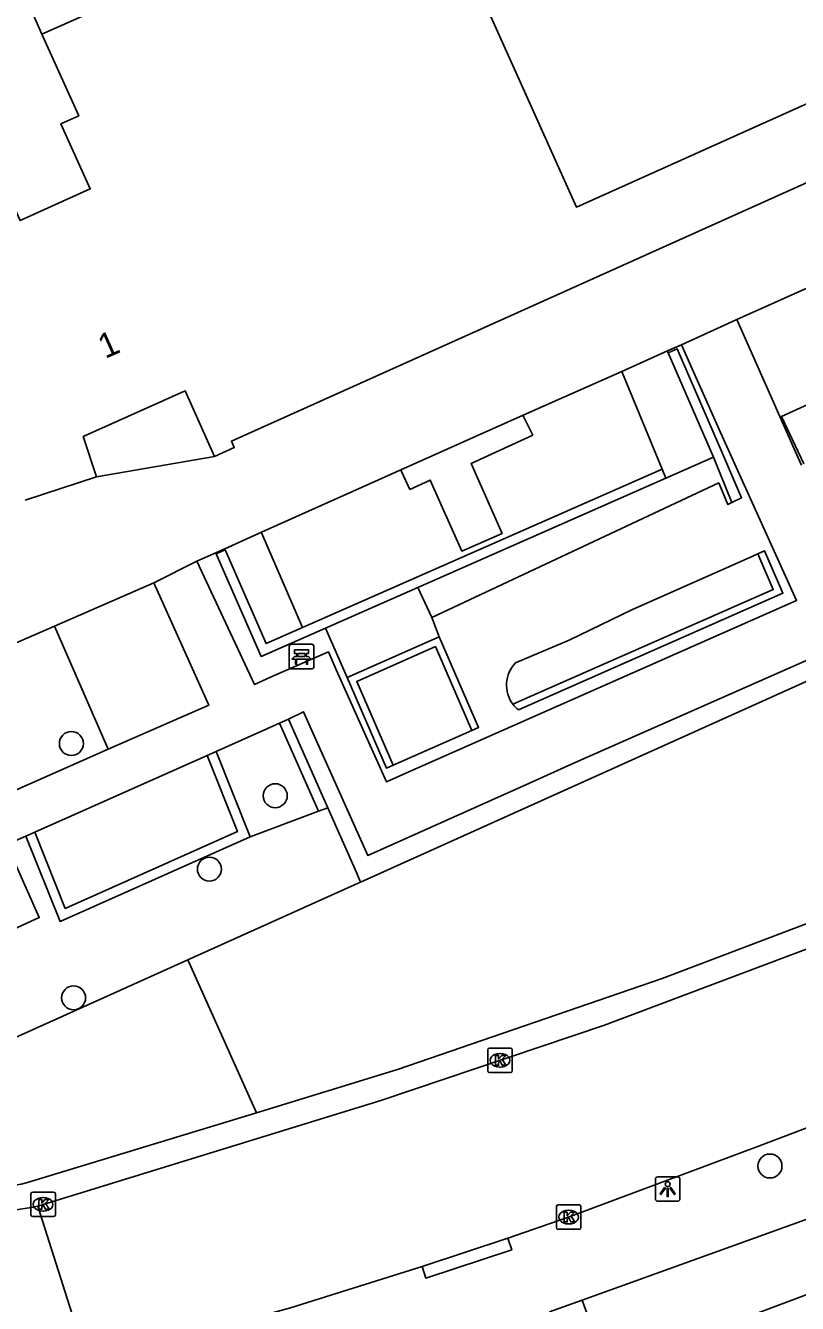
# Model space of a CAD drawing. Extents: x 161253 to 161848, y 384872 to 385383.
# Drawn here: x 161505.8 to 161537.3, y 385046.9 to 385099.1 of the extents above; entities that cross this region are included whole.
import ezdxf

# ---------------------------------------------------------------- set-up
doc = ezdxf.new("R2010")
doc.units = 0
for name, color, linetype in [('IMGEO_Bank', 7, 'Continuous'), ('IMGEO_Boom', 7, 'Continuous'), ('IMGEO_Groenvoorziening', 7, 'Continuous'), ('IMGEO_Haag', 7, 'Continuous'), ('IMGEO_Kolk', 7, 'Continuous'), ('IMGEO_Lichtpunt', 7, 'Continuous'), ('IMGEO_Pand', 7, 'Continuous'), ('IMGEO_Pand_nummerreeks', 7, 'Continuous'), ('IMGEO_Rijbaan_lokaal_open', 7, 'Continuous'), ('IMGEO_Voetpad_halfverhard', 7, 'Continuous'), ('IMGEO_Voetpad_open', 7, 'Continuous')]:
    doc.layers.add(name, color=color, linetype=linetype)

msp = doc.modelspace()

# ---------------------------------------------------------------- linework, layer by layer
at = {"layer": 'IMGEO_Bank'}
for p, q in [((161516.532, 385072.865), (161516.532, 385073.706)), ((161516.532, 385073.706), (161516.532, 385072.865)), ((161516.607, 385073.79), (161517.448, 385073.79)), ((161517.448, 385073.79), (161516.607, 385073.79)), ((161517.532, 385073.715), (161517.532, 385072.874)), ((161517.532, 385072.874), (161517.532, 385073.715)), ((161517.229, 385073.188), (161516.836, 385073.188)), ((161516.841, 385073.296), (161516.841, 385073.402)), ((161516.885, 385073.402), (161516.885, 385073.296)), ((161517.173, 385073.408), (161516.891, 385073.408)), ((161516.891, 385073.29), (161517.173, 385073.29)), ((161517.179, 385073.296), (161517.179, 385073.402)), ((161517.223, 385073.402), (161517.223, 385073.296)), ((161517.457, 385072.79), (161516.616, 385072.79)), ((161516.616, 385072.79), (161517.457, 385072.79))]:
    msp.add_line(p, q, dxfattribs=at)
for points in [[(161516.779, 385073.188), (161516.637, 385073.188), (161516.749, 385073.29), (161516.835, 385073.29)], [(161516.835, 385073.408), (161516.749, 385073.408), (161516.749, 385073.569), (161517.312, 385073.569), (161517.312, 385073.408), (161517.229, 385073.408)], [(161516.829, 385073.181), (161516.829, 385072.974), (161516.786, 385072.974), (161516.786, 385073.181)], [(161517.229, 385073.29), (161517.312, 385073.29), (161517.424, 385073.188), (161517.285, 385073.188)], [(161517.279, 385073.181), (161517.279, 385072.974), (161517.235, 385072.974), (161517.235, 385073.181)]]:
    msp.add_lwpolyline(points, dxfattribs=at)
for centre, radius, start, end in [((161516.61, 385073.712), 0.0779, 92.4484, 184.2845), ((161516.61, 385073.712), 0.0779, 92.4484, 184.2845), ((161517.454, 385073.712), 0.0779, 2.4484, 94.2845), ((161517.454, 385073.712), 0.0779, 2.4484, 94.2845), ((161516.779, 385073.181), 0.00671, 2.8957, 87.1043), ((161516.836, 385073.181), 0.00671, 92.8957, 177.1043), ((161516.834, 385073.401), 0.00671, 2.8957, 87.1043), ((161516.834, 385073.297), 0.00671, 272.8957, 357.1043), ((161516.891, 385073.401), 0.00671, 92.8957, 177.1043), ((161516.891, 385073.297), 0.00671, 182.8957, 267.1043), ((161517.173, 385073.401), 0.00671, 2.8957, 87.1043), ((161517.173, 385073.297), 0.00671, 272.8957, 357.1043), ((161517.23, 385073.401), 0.00671, 92.8957, 177.1043), ((161517.23, 385073.297), 0.00671, 182.8957, 267.1043), ((161517.228, 385073.181), 0.00671, 2.8957, 87.1043), ((161517.285, 385073.181), 0.00671, 92.8957, 177.1043), ((161516.61, 385072.868), 0.0779, 182.4484, 274.2845), ((161516.61, 385072.868), 0.0779, 182.4484, 274.2845), ((161517.454, 385072.868), 0.0779, 272.4484, 4.2845), ((161517.454, 385072.868), 0.0779, 272.4484, 4.2845)]:
    msp.add_arc(centre, radius, start, end, dxfattribs=at)
at = {"layer": 'IMGEO_Boom'}
for centre in [(161507.64, 385069.736), (161515.959, 385067.608), (161513.271, 385064.613), (161507.732, 385059.358), (161536.141, 385052.491)]:
    msp.add_circle(centre, 0.489, dxfattribs=at)
at = {"layer": 'IMGEO_Groenvoorziening'}
for points in [[(161583.611, 385090.971), (161578.405, 385089.13), (161576.826, 385088.455), (161555.221, 385080.061), (161546.898, 385076.445), (161519.439, 385064.08)], [(161531.994, 385085.686), (161531.96, 385085.764)], [(161530.093, 385084.931), (161530.127, 385084.856), (161531.742, 385080.936)], [(161521.079, 385080.91), (161521.108, 385080.845), (161521.452, 385080.111), (161522.284, 385080.497), (161523.576, 385077.597), (161525.215, 385078.314), (161523.949, 385081.175), (161526.462, 385082.332), (161526.104, 385083.067), (161526.072, 385083.138)], [(161531.894, 385080.566), (161533.832, 385081.43)], [(161534.588, 385079.584), (161534.415, 385079.501), (161534.05, 385080.378), (161522.346, 385074.89)], [(161517.068, 385074.475), (161515.417, 385078.314), (161515.394, 385078.365)], [(161513.896, 385077.693), (161513.917, 385077.647)], [(161525.765, 385073.031), (161527.955, 385073.955), (161530.531, 385075.211), (161535.315, 385077.339), (161535.644, 385077.485)], [(161520.77, 385068.857), (161523.981, 385070.274)], [(161517.723, 385066.971), (161514.93, 385065.934)], [(161519.439, 385064.08), (161519.266, 385064.472), (161518.098, 385067.11)], [(161505.007, 385065.612), (161506.332, 385062.63), (161504.42, 385061.76), (161502.997, 385064.717)], [(161519.439, 385064.08), (161519.074, 385063.916), (161512.396, 385060.909)], [(161501.094, 385055.82), (161512.396, 385060.909)], [(161512.396, 385060.909), (161515.187, 385054.666)]]:
    msp.add_lwpolyline(points, dxfattribs=at)
msp.add_arc((161526.68, 385072.123), 1.289, 135.2454, 217.3741, dxfattribs=at)
at = {"layer": 'IMGEO_Haag'}
for points in [[(161506.442, 385098.697), (161505.803, 385100.164)], [(161552.976, 385087.535), (161552.195, 385089.652), (161552.019, 385090.129), (161536.61, 385083.086), (161537.526, 385081.156)], [(161531.994, 385085.686), (161532.359, 385085.849), (161534.202, 385081.582), (161534.983, 385079.774), (161534.588, 385079.584)], [(161533.832, 385081.43), (161531.994, 385085.686)], [(161534.588, 385079.584), (161533.832, 385081.43)], [(161517.068, 385074.475), (161531.742, 385080.936)], [(161531.894, 385080.566), (161521.777, 385076.111)], [(161531.742, 385080.936), (161531.894, 385080.566)], [(161518.006, 385074.451), (161515.378, 385073.294), (161513.552, 385077.484), (161513.917, 385077.647)], [(161513.917, 385077.647), (161515.584, 385073.822), (161517.068, 385074.475)], [(161535.644, 385077.485), (161536.275, 385076.026), (161525.656, 385071.341)], [(161535.644, 385077.485), (161535.919, 385077.607), (161536.668, 385075.872), (161525.881, 385071.113)], [(161521.777, 385076.111), (161518.006, 385074.451)], [(161521.777, 385076.111), (161522.346, 385074.89)], [(161522.346, 385074.89), (161522.645, 385074.09)], [(161509.142, 385069.503), (161506.948, 385074.531)], [(161518.886, 385072.431), (161518.006, 385074.451)], [(161522.645, 385074.09), (161518.886, 385072.431)], [(161523.981, 385070.274), (161522.49, 385073.694), (161519.28, 385072.277), (161520.77, 385068.857)], [(161522.645, 385074.09), (161524.255, 385070.395), (161523.981, 385070.274)], [(161520.77, 385068.857), (161520.496, 385068.736), (161518.886, 385072.431)], [(161516.132, 385070.566), (161517.723, 385066.971)], [(161516.497, 385070.729), (161518.098, 385067.11)], [(161513.184, 385069.253), (161514.417, 385066.143), (161507.394, 385063.009), (161506.153, 385066.122)], [(161513.55, 385069.416), (161514.93, 385065.934)], [(161518.098, 385067.11), (161517.723, 385066.971)], [(161514.93, 385065.934), (161507.177, 385062.474), (161505.787, 385065.959)]]:
    msp.add_lwpolyline(points, dxfattribs=at)
msp.add_arc((161526.655, 385072.102), 1.256, 217.2933, 231.9478, dxfattribs=at)
at = {"layer": 'IMGEO_Kolk'}
for p, q in [((161524.626, 385056.381), (161524.626, 385057.233)), ((161524.701, 385057.307), (161525.553, 385057.307)), ((161525.114, 385057.087), (161525.139, 385057.087)), ((161525.627, 385057.233), (161525.627, 385056.381)), ((161525.137, 385056.527), (161525.112, 385056.527)), ((161525.553, 385056.307), (161524.701, 385056.307)), ((161505.988, 385050.5), (161505.988, 385051.352)), ((161506.063, 385051.426), (161506.915, 385051.426)), ((161506.989, 385051.352), (161506.989, 385050.5)), ((161506.476, 385051.206), (161506.501, 385051.206)), ((161527.428, 385049.98), (161527.428, 385050.832)), ((161527.503, 385050.906), (161528.355, 385050.906)), ((161528.429, 385050.832), (161528.429, 385049.98)), ((161506.915, 385050.426), (161506.063, 385050.426)), ((161506.499, 385050.646), (161506.474, 385050.646)), ((161527.916, 385050.686), (161527.941, 385050.686)), ((161528.355, 385049.906), (161527.503, 385049.906)), ((161527.939, 385050.126), (161527.914, 385050.126))]:
    msp.add_line(p, q, dxfattribs=at)
for points in [[(161524.626, 385056.381), (161524.626, 385057.233)], [(161524.701, 385057.307), (161525.553, 385057.307)], [(161524.947, 385057.007), (161525.07, 385057.007), (161525.07, 385056.856), (161525.2, 385057.007), (161525.364, 385057.007), (161525.218, 385056.856), (161525.371, 385056.607), (161525.219, 385056.607), (161525.134, 385056.771), (161525.07, 385056.704), (161525.07, 385056.607), (161524.947, 385056.607), (161524.947, 385057.007)], [(161525.627, 385057.233), (161525.627, 385056.381)], [(161525.553, 385056.307), (161524.701, 385056.307)], [(161505.988, 385050.5), (161505.988, 385051.352)], [(161506.063, 385051.426), (161506.915, 385051.426)], [(161506.989, 385051.352), (161506.989, 385050.5)], [(161506.309, 385051.126), (161506.432, 385051.126), (161506.432, 385050.975), (161506.562, 385051.126), (161506.726, 385051.126), (161506.58, 385050.975), (161506.733, 385050.726), (161506.581, 385050.726), (161506.496, 385050.89), (161506.432, 385050.823), (161506.432, 385050.726), (161506.309, 385050.726), (161506.309, 385051.126)], [(161527.428, 385049.98), (161527.428, 385050.832)], [(161527.503, 385050.906), (161528.355, 385050.906)], [(161528.429, 385050.832), (161528.429, 385049.98)], [(161506.915, 385050.426), (161506.063, 385050.426)], [(161527.749, 385050.606), (161527.872, 385050.606), (161527.872, 385050.455), (161528.002, 385050.606), (161528.166, 385050.606), (161528.02, 385050.455), (161528.173, 385050.206), (161528.021, 385050.206), (161527.936, 385050.37), (161527.872, 385050.303), (161527.872, 385050.206), (161527.749, 385050.206), (161527.749, 385050.606)], [(161528.355, 385049.906), (161527.503, 385049.906)]]:
    msp.add_lwpolyline(points, dxfattribs=at)
for centre, start, end in [((161524.703, 385057.231), 91.552, 178.448), ((161524.703, 385057.231), 91.552, 178.448), ((161525.551, 385057.231), 1.552, 88.448), ((161525.551, 385057.231), 1.552, 88.448), ((161524.703, 385056.383), 181.552, 268.448), ((161524.703, 385056.383), 181.552, 268.448), ((161525.551, 385056.383), 271.552, 358.448), ((161525.551, 385056.383), 271.552, 358.448), ((161506.065, 385051.35), 91.552, 178.448), ((161506.065, 385051.35), 91.552, 178.448), ((161506.913, 385051.35), 1.552, 88.448), ((161506.913, 385051.35), 1.552, 88.448), ((161527.505, 385050.83), 91.552, 178.448), ((161527.505, 385050.83), 91.552, 178.448), ((161528.353, 385050.83), 1.552, 88.448), ((161528.353, 385050.83), 1.552, 88.448), ((161506.065, 385050.502), 181.552, 268.448), ((161506.065, 385050.502), 181.552, 268.448), ((161506.913, 385050.502), 271.552, 358.448), ((161506.913, 385050.502), 271.552, 358.448), ((161527.505, 385049.982), 181.552, 268.448), ((161527.505, 385049.982), 181.552, 268.448), ((161528.353, 385049.982), 271.552, 358.448), ((161528.353, 385049.982), 271.552, 358.448)]:
    msp.add_arc(centre, 0.0765, start, end, dxfattribs=at)
for centre, major_axis, ratio, start_param, end_param in [((161525.113, 385056.807), (-0.387, 0.002), 0.722429, 4.712389, 7.853982), ((161525.138, 385056.807), (-0.39, 0.002), 0.717154, 1.570796, 4.712389), ((161506.475, 385050.926), (-0.387, 0.002), 0.722429, 4.712389, 7.853982), ((161506.5, 385050.926), (-0.39, 0.002), 0.717154, 1.570796, 4.712389), ((161527.915, 385050.406), (-0.387, 0.002), 0.722429, 4.712389, 7.853982), ((161527.94, 385050.406), (-0.39, 0.002), 0.717154, 1.570796, 4.712389)]:
    msp.add_ellipse(centre, major_axis=major_axis, ratio=ratio, start_param=start_param, end_param=end_param, dxfattribs=at)
at = {"layer": 'IMGEO_Lichtpunt'}
for p, q in [((161531.468, 385051.952), (161531.468, 385051.145)), ((161531.468, 385051.952), (161531.468, 385051.145)), ((161532.37, 385052.047), (161531.562, 385052.047)), ((161532.37, 385052.047), (161531.562, 385052.047)), ((161532.464, 385051.145), (161532.464, 385051.952)), ((161532.464, 385051.145), (161532.464, 385051.952)), ((161531.562, 385051.051), (161532.37, 385051.051)), ((161531.562, 385051.051), (161532.37, 385051.051))]:
    msp.add_line(p, q, dxfattribs=at)
for points in [[(161531.842, 385051.616), (161531.881, 385051.588), (161531.693, 385051.326), (161531.655, 385051.353), (161531.842, 385051.616)], [(161531.944, 385051.568), (161531.991, 385051.568), (161531.991, 385051.246), (161531.944, 385051.246), (161531.944, 385051.568)], [(161532.054, 385051.588), (161532.092, 385051.615), (161532.279, 385051.353), (161532.24, 385051.325), (161532.054, 385051.588)]]:
    msp.add_lwpolyline(points, dxfattribs=at)
msp.add_circle((161531.967, 385051.75), 0.0994, dxfattribs=at)
for centre, start, end in [((161531.562, 385051.952), 90, 180), ((161531.562, 385051.952), 90, 180), ((161532.37, 385051.952), 0, 90), ((161532.37, 385051.952), 0, 90), ((161531.562, 385051.145), 180, 270), ((161531.562, 385051.145), 180, 270), ((161532.37, 385051.145), 270, 0), ((161532.37, 385051.145), 270, 360)]:
    msp.add_arc(centre, 0.0946, start, end, dxfattribs=at)
at = {"layer": 'IMGEO_Pand'}
for points in [[(161544.216, 385098.993), (161543.409, 385098.631), (161543.475, 385098.484), (161528.242, 385091.641), (161524.736, 385099.445), (161540.026, 385106.314), (161540.114, 385106.118), (161540.85, 385106.449)], [(161509.432, 385100.917), (161509.76, 385100.187), (161506.442, 385098.697)], [(161506.442, 385098.697), (161507.939, 385095.366), (161507.216, 385095.041), (161508.413, 385092.378), (161505.548, 385091.091), (161505.089, 385092.114)], [(161544.216, 385098.993), (161545.617, 385095.875), (161544.78, 385095.5), (161544.654, 385095.78), (161514.171, 385082.086), (161514.288, 385081.826), (161513.477, 385081.462)], [(161508.662, 385080.628), (161508.122, 385082.268), (161512.277, 385084.134), (161513.477, 385081.462)], [(161508.662, 385080.628), (161505.758, 385079.671)], [(161535.556, 385046.459), (161541.46, 385048.676)]]:
    msp.add_lwpolyline(points, dxfattribs=at)
at = {"layer": 'IMGEO_Rijbaan_lokaal_open'}
for points in [[(161506.266, 385050.857), (161520.264, 385055.172), (161529.392, 385058.239), (161585.906, 385079.534), (161586.502, 385079.759)], [(161590.259, 385074.054), (161535.71, 385053.309), (161527.874, 385050.388), (161525.446, 385049.549)], [(161508.319, 385044.433), (161506.266, 385050.857)], [(161521.95, 385048.386), (161525.446, 385049.549)], [(161521.95, 385048.386), (161516.58, 385046.703), (161508.319, 385044.433)]]:
    msp.add_lwpolyline(points, dxfattribs=at)
msp.add_arc((161504.733, 385057.383), 6.704, 211.5543, 283.2161, dxfattribs=at)
at = {"layer": 'IMGEO_Voetpad_halfverhard'}
for points in [[(161516.497, 385070.729), (161517.114, 385071.036), (161517.388, 385070.417), (161519.737, 385065.162), (161526.333, 385068.119), (161528.198, 385068.97), (161530.726, 385070.086), (161581.929, 385092.695), (161582.198, 385092.828), (161582.461, 385092.975)], [(161534.793, 385087.051), (161537.292, 385081.408), (161537.421, 385081.109)], [(161512.765, 385077.186), (161515.111, 385072.146), (161515.768, 385072.447), (161518.13, 385073.48), (161518.462, 385072.714), (161520.503, 385068.174), (161521.411, 385068.578), (161537.224, 385075.58), (161534.128, 385082.433), (161532.526, 385086.017)], [(161509.142, 385069.503), (161512.497, 385070.981), (161513.245, 385071.304), (161511.002, 385076.293)], [(161513.55, 385069.416), (161516.132, 385070.566)], [(161516.132, 385070.566), (161516.497, 385070.729)], [(161503.752, 385067.128), (161509.142, 385069.503)], [(161506.153, 385066.122), (161513.184, 385069.253)], [(161513.184, 385069.253), (161513.55, 385069.416)], [(161505.787, 385065.959), (161505.007, 385065.612)], [(161505.787, 385065.959), (161506.153, 385066.122)]]:
    msp.add_lwpolyline(points, dxfattribs=at)
at = {"layer": 'IMGEO_Voetpad_open'}
for points in [[(161550.712, 385094.175), (161534.793, 385087.051)], [(161532.526, 385086.017), (161534.793, 385087.051)], [(161531.96, 385085.764), (161530.093, 385084.931)], [(161532.526, 385086.017), (161531.96, 385085.764)], [(161530.093, 385084.931), (161526.072, 385083.138)], [(161526.072, 385083.138), (161521.079, 385080.91)], [(161513.477, 385081.462), (161508.662, 385080.628)], [(161521.079, 385080.91), (161519.104, 385080.029), (161515.394, 385078.365)], [(161584.888, 385080.338), (161531.74, 385060.145), (161520.946, 385056.425), (161515.187, 385054.666)], [(161515.394, 385078.365), (161513.896, 385077.693)], [(161513.896, 385077.693), (161512.765, 385077.186)], [(161511.002, 385076.293), (161512.765, 385077.186)], [(161511.002, 385076.293), (161506.948, 385074.531)], [(161506.948, 385074.531), (161501.565, 385072.192)], [(161528.473, 385047.01), (161538.894, 385050.769), (161591.594, 385070.858), (161592.95, 385067.024)], [(161515.187, 385054.666), (161505.845, 385051.813)], [(161525.446, 385049.549), (161525.603, 385049.075), (161522.107, 385047.913), (161521.95, 385048.386)], [(161527.147, 385046.532), (161528.473, 385047.01)], [(161528.473, 385047.01), (161529.493, 385044.181)]]:
    msp.add_lwpolyline(points, dxfattribs=at)
msp.add_arc((161505.014, 385054.592), 2.901, 207.6488, 286.6553, dxfattribs=at)

# ---------------------------------------------------------------- texts
at = {"layer": 'IMGEO_Pand_nummerreeks'}
msp.add_text('1', height=1, rotation=24.1847, dxfattribs=at).set_placement((161509.02, 385085.433))

doc.saveas('drawing.dxf')
